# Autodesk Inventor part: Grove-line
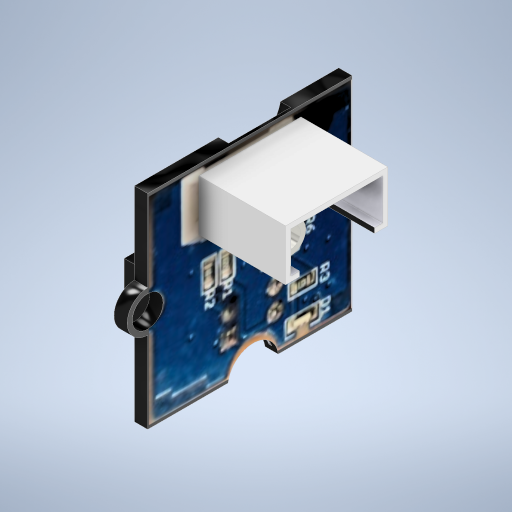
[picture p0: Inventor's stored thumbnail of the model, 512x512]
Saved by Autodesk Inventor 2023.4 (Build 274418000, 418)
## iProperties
Created: 2022-12
Part Number: Grove-line
Material: Générique
Document SubType Name: Modeling
Designer: ecuenot
Density: 1 g/cm^3
Appearance: Noir
Author: ecuenot
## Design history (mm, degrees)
sketch "Esquisse1"
  geometry: L1 (20, 0)-(20, -20); L2 (0, -20)-(0, 0); L3 (11.5, 0)-(12, 0); L4 (10, 0)-(8, 0); L5 (0, 0)-(8, 0); L6 (11.5, 0)-(20, 0); L7 (20, -20)-(12, -20); L8 (8, -20)-(0, -20); C1 r 1.5 at (10, -20); A1 r 2 centre (10, 0) between (12, 0) and (8, 0); A2 r 2 centre (10, -20) between (8, -20) and (12, -20); 2 further points
  constraints: 16 end point, 5 parallel, 4 point on circle, 3 centre point, 2 coincident, 2 horizontal, 2 perpendicular, 1 horizontal alignment, 2 other
  dimensions: "d0" = 20 distance of L1.end L2.start; "d1" = 20 distance of L1.start L1.end
extrude "Extrusion1" new body sketch "Esquisse1" distance "d9" = 1.3; taper "d10" = 0 deg
sketch "Esquisse6"
  geometry: L1 (20, 20)-(0, 20) reference; L2 (15, 14)-(5, 14); L3 (5, 14)-(5, 19); L4 (5, 19)-(15, 19); L5 (15, 19)-(15, 14); L6 (15, 14)-(5, 19); L7 (5, 14)-(15, 19); 2 further points
  constraints: 12 end point, 2 midpoint, 2 parallel, 1 horizontal, 1 perpendicular
  dimensions: "d36" = 10 distance of L3.end L4.end; "d37" = 5 distance of L2.end L3.end
extrude "Extrusion4" join sketch "Esquisse6" distance "d38" = 8.5; taper "d39" = 0 deg
feature "Coque2" dims "d41" = 0.5
sketch "Esquisse7"
  geometry: L1 (3.749, 1.295)-(8.801, 1.295); L2 (8.801, 1.295)-(8.801, 8.634); L3 (8.801, 8.634)-(3.749, 8.634); L4 (3.749, 8.634)-(3.749, 1.295); L5 (3.749, 1.295)-(8.801, 8.634); L6 (8.801, 1.295)-(3.749, 8.634); 1 further point
  constraints: 12 end point, 2 parallel, 1 horizontal, 1 perpendicular
extrude "Extrusion5" cut sketch "Esquisse7" stored distance "d44" = 8.5; taper "d45" = 0 deg
sketch "Esquisse8" dims "d52" = 10
  geometry: L1 (-4.5, 7.064)-(-14.5, 7.064) reference; C1 r 0.5 at (-12.533, 4.536); C2 r 0.5 at (-10.533, 4.536); C3 r 0.5 at (-8.533, 4.536); C4 r 0.5 at (-6.533, 4.536); 1 further point
  constraints: 4 centre point, 1 horizontal, 6 other
  dimensions: "d46" = 1 diameter of C1; "d49" = 2 distance of C1.centre C2.centre
extrude "Extrusion6" join sketch "Esquisse8" distance "d54" = 7; taper "d55" = 0 deg
fillet "Congé2" dims "d56" = 0.5
sketch "Esquisse11"
  geometry: L1 (0, 0)-(20, 0) reference; C1 r 2.474 at (10.322, -0.327); 2 further points
  constraints: 1 centre point
extrude "Extrusion7" cut sketch "Esquisse11" distance "d73" = 7; taper "d74" = 0 deg
sketch "Esquisse15"
  geometry: L1 (0.092, 0.275)-(0.092, 19.696); L2 (0.092, 19.696)-(20.093, 19.696); L3 (20.093, 19.696)-(20.093, 0.275); L4 (20.093, 0.275)-(0.092, 0.275); 1 further point; 1 other entity
  constraints: 2 other
  node "Image13"
sketch "Esquisse16"
  geometry: L1 (-20, 20)-(0, 20) reference; L2 (0, 20)-(0, 12) reference; L3 (-20, 0.406)-(-20, 19.014); L4 (-20, 19.014)-(-0.184, 19.014); L5 (-0.184, 19.014)-(-0.184, 0.406); L6 (-0.184, 0.406)-(-20, 0.406); 1 further point; 1 other entity
  constraints: 2 other
feature "Décalcomanie7" sketch "Esquisse16"
feature "Décalcomanie8"
sketch "Esquisse17"
  geometry: C1 r 3.1 at (-11.257, 20.622); 1 further point
  constraints: 1 centre point
extrude "Extrusion10" cut sketch "Esquisse17" distance "d154" = 1; taper "d155" = 0 deg
sketch "Esquisse18"
  geometry: L1 (-11.531, 13.241)-(-7.853, 13.241); L2 (-7.853, 13.241)-(-7.853, 8.784); L3 (-7.853, 8.784)-(-11.531, 8.784); L4 (-11.531, 8.784)-(-11.531, 13.241); 1 further point
  constraints: 8 end point, 2 parallel, 1 horizontal, 1 perpendicular
extrude "Extrusion11" join sketch "Esquisse18" distance "d188" = 1; taper "d189" = 0 deg
sketch "Esquisse20"
  geometry: L1 (-14.69, 8.351)-(-4.998, 8.351); L2 (-4.998, 8.351)-(-4.998, 3.245); L3 (-4.998, 3.245)-(-14.69, 3.245); L4 (-14.69, 3.245)-(-14.69, 8.351); 1 further point
  constraints: 8 end point, 2 parallel, 1 horizontal, 1 perpendicular
extrude "Extrusion12" join sketch "Esquisse20" distance "d190" = 6; taper "d191" = 0 deg
sketch "Esquisse21"
  geometry: L1 (-14.321, 7.966)-(-10.104, 7.966); L2 (-10.104, 7.966)-(-10.104, 3.564); L3 (-10.104, 3.564)-(-14.321, 3.564); L4 (-14.321, 3.564)-(-14.321, 7.966); L5 (-9.709, 7.966)-(-5.385, 7.966); L6 (-5.385, 7.966)-(-5.385, 3.564); L7 (-5.385, 3.564)-(-9.709, 3.564); L8 (-9.709, 3.564)-(-9.709, 7.966); 1 further point
  constraints: 16 end point, 4 parallel, 2 horizontal, 2 perpendicular, 2 point on line
extrude "Extrusion13" cut sketch "Esquisse21" distance "d192" = 4; taper "d193" = 0 deg
node "Plan de construction1"
sketch "Esquisse23"
  geometry: L1 (-14.321, 3.564)-(-14.321, 7.966) reference; L2 (-14.321, 5.73)-(-5.24, 5.73); C1 r 1.971 at (-12.201, 5.73); C2 r 2.089 at (-7.553, 5.73); 5 further points
  constraints: 3 point on line, 2 centre point, 2 end point, 1 horizontal
revolve "Révolution2" sketch "Esquisse23" stored, may be unused: angle "d196" = 90 deg
sketch "Esquisse24"
  geometry: C1 r 1.515 at (12.955, 10.237); C2 r 0.991 at (12.955, 10.237); 1 further point
  constraints: 2 centre point, 1 coincident
extrude "Extrusion14" join sketch "Esquisse24" distance "d197" = 1; taper "d198" = 0 deg
node "Solide1"
node "Image14"
other parameters: "d195" = -3
